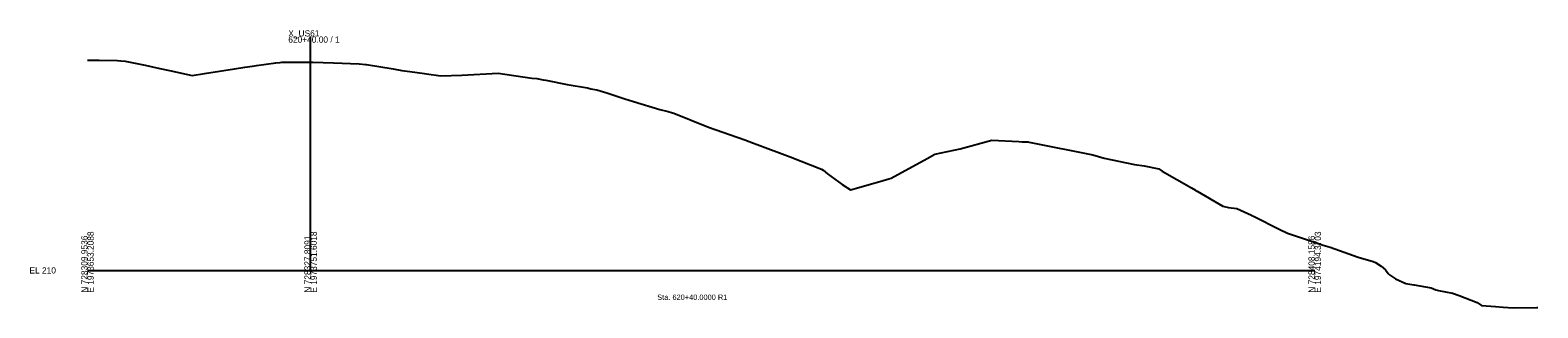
# Model space of a CAD drawing. Extents: x -26 to 1629, y -25 to 9635.
# Drawn here: x -26 to 650, y 983 to 1108 of the extents above; entities that cross this region are included whole.
import ezdxf

# ---------------------------------------------------------------- set-up
doc = ezdxf.new("R2010")
doc.units = 0
for name, color, linetype in [('Draft_XS_Grid', 7, 'Continuous'), ('Draft_XS_Text', 7, 'Continuous'), ('DTM_X_GROUND', 7, 'Continuous'), ('XS_CELL', 7, 'Continuous')]:
    doc.layers.add(name, color=color, linetype=linetype)

msp = doc.modelspace()

# ---------------------------------------------------------------- linework, layer by layer
at = {"layer": 'DTM_X_GROUND'}
msp.add_lwpolyline([(0, 1094.4), (5.2, 1094.32), (13.38, 1094.21), (14.97, 1094.1), (16.86, 1093.97), (25.91, 1092.05), (31.12, 1090.95), (38.84, 1089.27), (44.82, 1087.94), (46.91, 1087.47), (52.49, 1088.34), (65.92, 1090.43), (70.58, 1091.15), (73.89, 1091.65), (75.69, 1091.92), (84.43, 1093.22), (86.39, 1093.34), (87.13, 1093.39), (87.58, 1093.39), (101.06, 1093.45), (110.3, 1093.13), (121.76, 1092.74), (124.57, 1092.46), (125.06, 1092.41), (136.98, 1090.4), (140.92, 1089.73), (144.53, 1089.23), (151.06, 1088.39), (152, 1088.27), (158.3, 1087.36), (167.81, 1087.61), (184.05, 1088.48), (199.1, 1086.31), (201.45, 1086.06), (204.18, 1085.56), (205.48, 1085.37), (214.93, 1083.46), (224.07, 1081.89), (225.6, 1081.55), (228.33, 1081.1), (232.82, 1079.76), (240.86, 1077.04), (244.72, 1075.79), (256.56, 1072.21), (260.31, 1071.35), (262.22, 1070.71), (262.76, 1070.54), (278.32, 1064.34), (294.56, 1058.65), (298.42, 1057.15), (300.12, 1056.51), (314.9, 1050.94), (328.94, 1045.46), (329.78, 1044.93), (331.68, 1043.31), (334.98, 1040.93), (338.24, 1038.57), (341.99, 1036.1), (354.06, 1039.64), (359.07, 1041.11), (360.15, 1041.42), (376.3, 1050.17), (379.79, 1052.21), (391.06, 1054.52), (405.31, 1058.45), (417.38, 1057.84), (418.86, 1057.77), (421.13, 1057.66), (421.66, 1057.63), (421.86, 1057.59), (422.8, 1057.45), (450.52, 1051.91), (455.59, 1050.34), (469.21, 1047.47), (473.62, 1046.88), (480.13, 1045.59), (481.66, 1044.47), (494.75, 1037.04), (496.58, 1035.97), (496.89, 1035.78), (497.36, 1035.53), (508.82, 1028.78), (511.32, 1028.2), (515.1, 1027.76), (521.62, 1024.76), (521.88, 1024.65), (522.54, 1024.35), (534.31, 1018.39), (537.87, 1016.75), (545.47, 1014.11), (553.85, 1011.31), (556.97, 1010.36), (559.07, 1009.62), (569.48, 1005.89), (576.24, 1003.93), (577.28, 1003.59), (579.84, 1001.84), (581.72, 1000.3), (582.97, 998.68), (583.51, 997.94), (586.22, 996.25), (590.91, 994.1), (594.36, 993.49), (594.52, 993.48), (602.21, 992.1), (604.26, 991.32), (605.53, 991.05), (611.68, 989.82), (614.77, 988.72), (622.87, 985.57), (624.73, 984.23), (630.99, 983.73), (634.52, 983.5), (638.96, 983.17), (649.57, 983.31), (650, 983.31)], dxfattribs=at)
at = {"layer": 'XS_CELL'}
for p, q in [((100, 1000), (100, 1105)), ((0, 1000), (100, 1000)), ((100, 1000), (550, 1000))]:
    msp.add_line(p, q, dxfattribs=at)

# ---------------------------------------------------------------- texts
at = {"layer": 'Draft_XS_Grid'}
msp.add_text('-', height=0.0001, dxfattribs=at).set_placement((0, 1000))
at = {"layer": 'Draft_XS_Text'}
msp.add_text('Sta. 620+40.0000 R1', height=2.4, dxfattribs=at).set_placement((255.34, 986.75))
at = {"layer": 'XS_CELL'}
for s, p in [('X_US61', (90, 1105)), ('620+40.00 / 1', (90, 1102.2)), ('EL 210', (-26, 998.6))]:
    msp.add_text(s, height=2.8, dxfattribs=at).set_placement(p)
for s, p in [('N 728309.9536', (0, 990)), ('E 1973653.2088', (2.8, 990)), ('N 728327.8091', (100, 990)), ('E 1973751.6018', (102.8, 990)), ('N 728408.1586', (550, 990)), ('E 1974194.3703', (552.8, 990))]:
    msp.add_text(s, height=2.8, rotation=90, dxfattribs=at).set_placement(p)

doc.saveas('drawing.dxf')
